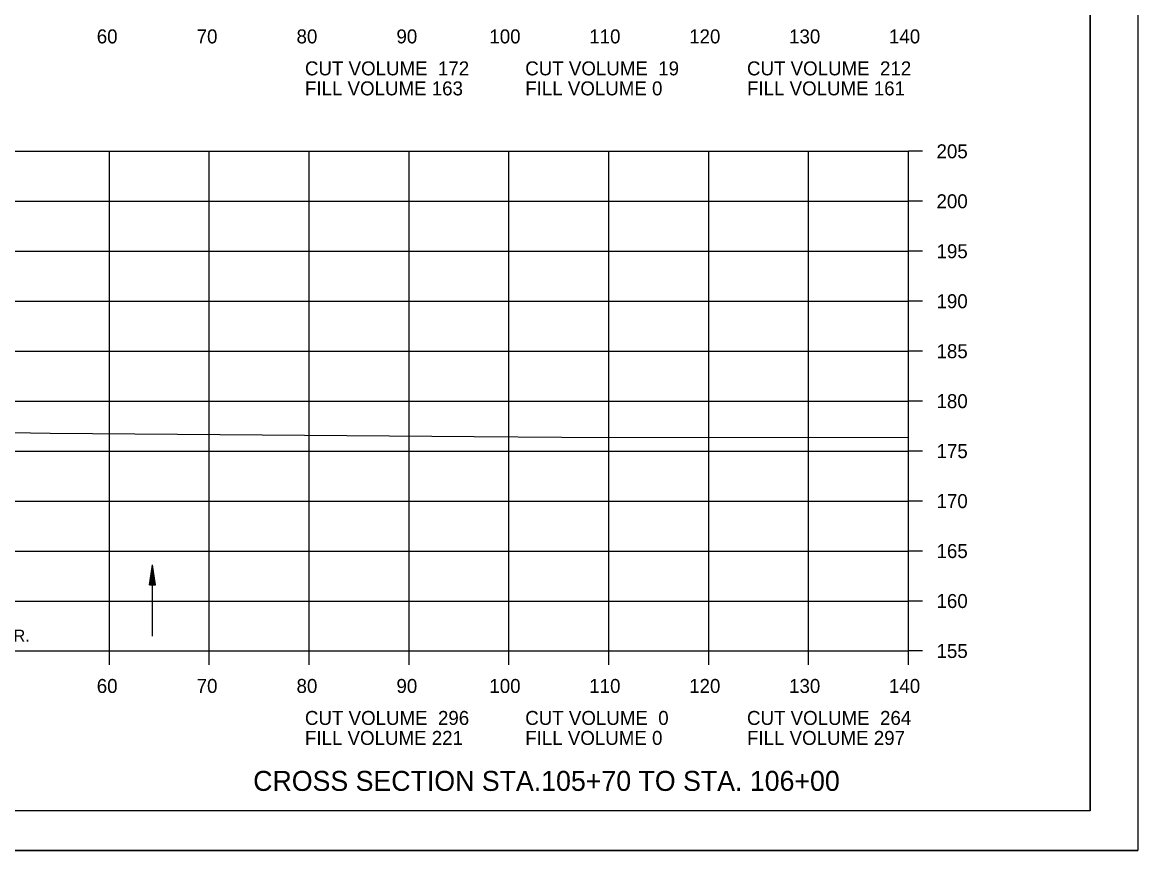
# Model space of a CAD drawing. Extents: x 1372132 to 1372465, y 380083 to 381790.
# Drawn here: x 1372353.3 to 1372464.9, y 380510.2 to 380593.1 of the extents above; entities that cross this region are included whole.
import ezdxf

# ---------------------------------------------------------------- set-up
doc = ezdxf.new("R2010")
doc.units = 0
for name, color, linetype in [('R_Axis', 7, 'Continuous'), ('R_Axis Annot', 7, 'Continuous'), ('R_Border', 7, 'Continuous'), ('R_Dimension', 7, 'Continuous'), ('R_Draft', 7, 'Continuous'), ('R_Exist Surface', 7, 'Continuous'), ('R_Grid', 7, 'Continuous'), ('R_No Plot', 7, 'Continuous')]:
    doc.layers.add(name, color=color, linetype=linetype)

msp = doc.modelspace()

# ---------------------------------------------------------------- linework, layer by layer
at = {"layer": 'R_Axis'}
for p, q in [((1372442.01, 380530.15), (1372442.01, 380580.15)), ((1372443.41, 380580.15), (1372442.01, 380580.15)), ((1372443.41, 380575.15), (1372442.01, 380575.15)), ((1372443.41, 380570.15), (1372442.01, 380570.15)), ((1372443.41, 380565.15), (1372442.01, 380565.15)), ((1372443.41, 380560.15), (1372442.01, 380560.15)), ((1372443.41, 380555.15), (1372442.01, 380555.15)), ((1372443.41, 380550.15), (1372442.01, 380550.15)), ((1372443.41, 380545.15), (1372442.01, 380545.15)), ((1372443.41, 380540.15), (1372442.01, 380540.15)), ((1372443.41, 380535.15), (1372442.01, 380535.15)), ((1372162.01, 380530.15), (1372442.01, 380530.15)), ((1372362.01, 380528.75), (1372362.01, 380530.15)), ((1372372.01, 380528.75), (1372372.01, 380530.15)), ((1372382.01, 380528.75), (1372382.01, 380530.15)), ((1372392.01, 380528.75), (1372392.01, 380530.15)), ((1372402.01, 380528.75), (1372402.01, 380530.15)), ((1372412.01, 380528.75), (1372412.01, 380530.15)), ((1372422.01, 380528.75), (1372422.01, 380530.15)), ((1372432.01, 380528.75), (1372432.01, 380530.15)), ((1372442.01, 380528.75), (1372442.01, 380530.15)), ((1372443.41, 380530.15), (1372442.01, 380530.15))]:
    msp.add_line(p, q, dxfattribs=at)
at = {"layer": 'R_Border'}
for q in [(1372460.19, 380719.61), (1372144.01, 380514.15)]:
    msp.add_line((1372460.19, 380514.15), q, dxfattribs=at)
at = {"layer": 'R_Dimension'}
for p, q in [((1372366.04, 380536.78), (1372366.34, 380538.78)), ((1372366.04, 380536.78), (1372366.34, 380538.78)), ((1372366.09, 380536.78), (1372366.34, 380538.44)), ((1372366.09, 380536.78), (1372366.34, 380538.44)), ((1372366.14, 380536.78), (1372366.34, 380538.1)), ((1372366.14, 380536.78), (1372366.34, 380538.1)), ((1372366.19, 380536.78), (1372366.34, 380537.77)), ((1372366.19, 380536.78), (1372366.34, 380537.77)), ((1372366.64, 380536.78), (1372366.34, 380538.78)), ((1372366.64, 380536.78), (1372366.34, 380538.78)), ((1372366.59, 380536.78), (1372366.34, 380538.44)), ((1372366.59, 380536.78), (1372366.34, 380538.44)), ((1372366.54, 380536.78), (1372366.34, 380538.1)), ((1372366.54, 380536.78), (1372366.34, 380538.1)), ((1372366.49, 380536.78), (1372366.34, 380537.77)), ((1372366.49, 380536.78), (1372366.34, 380537.77)), ((1372366.04, 380536.78), (1372366.64, 380536.78)), ((1372366.04, 380536.78), (1372366.64, 380536.78)), ((1372366.24, 380536.78), (1372366.34, 380537.43)), ((1372366.24, 380536.78), (1372366.34, 380537.43)), ((1372366.29, 380536.78), (1372366.34, 380537.09)), ((1372366.29, 380536.78), (1372366.34, 380537.09)), ((1372366.43, 380536.78), (1372366.34, 380537.43)), ((1372366.43, 380536.78), (1372366.34, 380537.43)), ((1372366.38, 380536.78), (1372366.34, 380537.09)), ((1372366.38, 380536.78), (1372366.34, 380537.09))]:
    msp.add_line(p, q, dxfattribs=at)
at = {"layer": 'R_Draft'}
msp.add_line((1372366.34, 380531.64), (1372366.34, 380538.78), dxfattribs=at)
at = {"layer": 'R_Exist Surface'}
msp.add_lwpolyline([(1372352.16, 380552), (1372356.1, 380551.96), (1372398.54, 380551.62), (1372407.31, 380551.53), (1372442.01, 380551.5)], dxfattribs=at)
at = {"layer": 'R_Grid'}
for p, q in [((1372162.01, 380580.15), (1372442.01, 380580.15)), ((1372362.01, 380530.15), (1372362.01, 380580.15)), ((1372372.01, 380530.15), (1372372.01, 380580.15)), ((1372382.01, 380530.15), (1372382.01, 380580.15)), ((1372392.01, 380530.15), (1372392.01, 380580.15)), ((1372402.01, 380530.15), (1372402.01, 380580.15)), ((1372412.01, 380530.15), (1372412.01, 380580.15)), ((1372422.01, 380530.15), (1372422.01, 380580.15)), ((1372432.01, 380530.15), (1372432.01, 380580.15)), ((1372442.01, 380530.15), (1372442.01, 380580.15)), ((1372162.01, 380575.15), (1372442.01, 380575.15)), ((1372162.01, 380570.15), (1372442.01, 380570.15)), ((1372162.01, 380565.15), (1372442.01, 380565.15)), ((1372162.01, 380560.15), (1372442.01, 380560.15)), ((1372162.01, 380555.15), (1372442.01, 380555.15)), ((1372162.01, 380550.15), (1372442.01, 380550.15)), ((1372162.01, 380545.15), (1372442.01, 380545.15)), ((1372162.01, 380540.15), (1372442.01, 380540.15)), ((1372162.01, 380535.15), (1372442.01, 380535.15)), ((1372162.01, 380530.15), (1372442.01, 380530.15))]:
    msp.add_line(p, q, dxfattribs=at)
at = {"layer": 'R_No Plot'}
msp.add_line((1372131.61, 380510.17), (1372464.95, 380510.17), dxfattribs=at)
for points in [[(1372131.61, 380723.5), (1372464.95, 380723.5), (1372464.95, 380510.17), (1372131.61, 380510.17)], [(1372377.93, 380719.61), (1372377.93, 380709.73), (1372413.67, 380709.73), (1372413.67, 380706.81), (1372436.87, 380706.81), (1372436.87, 380682.48), (1372460.19, 380682.48), (1372460.19, 380514.15), (1372144.01, 380514.15), (1372144.01, 380719.61)]]:
    msp.add_lwpolyline(points, close=True, dxfattribs=at)

# ---------------------------------------------------------------- texts
at = {"layer": 'R_Axis Annot'}
for s, p in [('60', (1372360.75, 380590.95)), ('70', (1372370.75, 380590.95)), ('80', (1372380.75, 380590.95)), ('90', (1372390.75, 380590.95)), ('100', (1372400.05, 380590.95)), ('110', (1372410.05, 380590.95)), ('120', (1372420.05, 380590.95)), ('130', (1372430.05, 380590.95)), ('140', (1372440.05, 380590.95)), ('CUT VOLUME  172', (1372381.59, 380587.75)), ('CUT VOLUME  19', (1372403.64, 380587.75)), ('CUT VOLUME  212', (1372425.84, 380587.75)), ('FILL VOLUME 163', (1372381.59, 380585.75)), ('FILL VOLUME 0', (1372403.64, 380585.75)), ('FILL VOLUME 161', (1372425.84, 380585.75)), ('205', (1372444.81, 380579.45)), ('200', (1372444.81, 380574.45)), ('195', (1372444.81, 380569.45)), ('190', (1372444.81, 380564.45)), ('185', (1372444.81, 380559.45)), ('180', (1372444.81, 380554.45)), ('175', (1372444.81, 380549.45)), ('170', (1372444.81, 380544.45)), ('165', (1372444.81, 380539.45)), ('160', (1372444.81, 380534.45)), ('155', (1372444.81, 380529.45)), ('60', (1372360.75, 380525.95)), ('70', (1372370.75, 380525.95)), ('80', (1372380.75, 380525.95)), ('90', (1372390.75, 380525.95)), ('100', (1372400.05, 380525.95)), ('110', (1372410.05, 380525.95)), ('120', (1372420.05, 380525.95)), ('130', (1372430.05, 380525.95)), ('140', (1372440.05, 380525.95)), ('CUT VOLUME  296', (1372381.59, 380522.75)), ('CUT VOLUME  0', (1372403.64, 380522.75)), ('CUT VOLUME  264', (1372425.84, 380522.75)), ('FILL VOLUME 221', (1372381.59, 380520.75)), ('FILL VOLUME 0', (1372403.64, 380520.75)), ('FILL VOLUME 297', (1372425.84, 380520.75))]:
    msp.add_text(s, height=1.4, dxfattribs=at).set_placement(p)
at = {"layer": 'R_Draft'}
for s, height, p in [('BEGIN 2.56% RT. DT. GR.', 1.2, (1372334.69, 380531.08)), ('CROSS SECTION STA.105+70 TO STA. 106+00', 2, (1372376.41, 380516.15))]:
    msp.add_text(s, height=height, dxfattribs=at).set_placement(p)

doc.saveas('drawing.dxf')
